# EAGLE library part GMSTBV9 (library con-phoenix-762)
PHOENIX
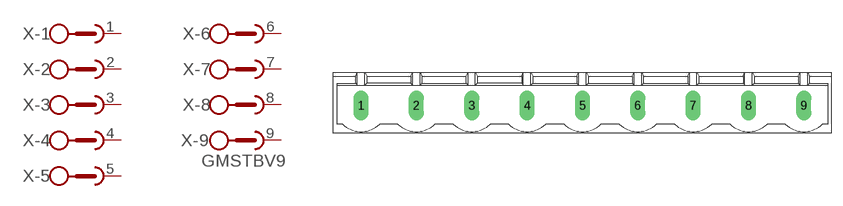
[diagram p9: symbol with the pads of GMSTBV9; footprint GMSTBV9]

Designator prefix X; gates -1=SKB -2=SKB -3=SKB -4=SKB -5=SKB -6=SKB -7=SKB -8=SKB -9=SKBV

## GMSTBV9 (OC_FARNELL: unknown; OC_NEWARK: unknown)  [GMSTBV9]
1  -1:1  pas
2  -2:1  pas
3  -3:1  pas
4  -4:1  pas
5  -5:1  pas
6  -6:1  pas
7  -7:1  pas
8  -8:1  pas
9  -9:1  pas

## Footprint GMSTBV9 (pad centres in mm)
PHOENIX
drill 1.397 long: 1 -30.48,0; 2 -22.86,0; 3 -15.24,0; 4 -7.62,0; 5 0,0; 6 7.62,0; 7 15.24,0; 8 22.86,0; 9 30.48,0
